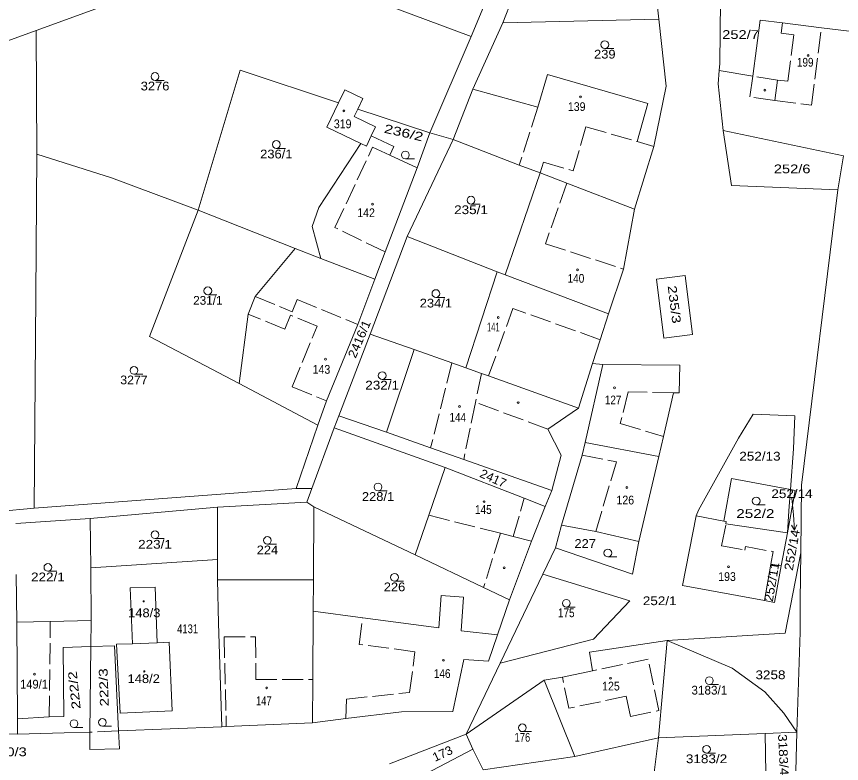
# Model space of a CAD drawing. Extents: x -590528 to -586543, y -1119609 to -1116685.
# Drawn here: x -588764.7 to -588604.8, y -1118121.8 to -1117977 of the extents above; entities that cross this region are included whole.
import ezdxf
from ezdxf.enums import TextEntityAlignment as Align

# ---------------------------------------------------------------- set-up
doc = ezdxf.new("R2010")
doc.units = 0
doc.header["$LTSCALE"] = 0.68
doc.linetypes.add('LONG_DASHED', pattern=[7.5, 6, -1.5])
for name, color, linetype, lineweight in [('1', 7, 'Continuous', 13), ('2', 7, 'LONG_DASHED', 13), ('3', 7, 'Continuous', 13), ('6', 7, 'Continuous', 13)]:
    doc.layers.add(name, color=color, linetype=linetype, lineweight=lineweight)

msp = doc.modelspace()

# ---------------------------------------------------------------- linework, layer by layer
at = {"layer": '1'}
for p, q in [((-588670.43, -1117978.2), (-588661.24, -1117954.68)), ((-588640.24, -1117977.46), (-588641.88, -1117961.86)), ((-588760.88, -1117979.71), (-588719.92, -1117964.64)), ((-588719.92, -1117964.64), (-588676.56, -1117980.86)), ((-588676.56, -1117980.86), (-588669.62, -1117964.03)), ((-588628.23, -1117973.84), (-588628.41, -1117986.05)), ((-588640.24, -1117977.46), (-588638.79, -1117990.47)), ((-588621.96, -1117988.54), (-588620.54, -1117977.65)), ((-588616.22, -1117978.21), (-588620.54, -1117977.65)), ((-588608.69, -1117979.19), (-588616.22, -1117978.21)), ((-588608.69, -1117979.19), (-588600.89, -1117980.09)), ((-588760.74, -1118003.63), (-588760.88, -1117979.71)), ((-588621.96, -1117988.54), (-588628.51, -1117987.46)), ((-588697.59, -1117992.86), (-588701.09, -1117991.21)), ((-588676.24, -1117991.07), (-588680.09, -1118000.83)), ((-588676.24, -1117991.07), (-588663.65, -1117994.53)), ((-588638.79, -1117990.47), (-588641.19, -1118002.14)), ((-588698.58, -1117994.92), (-588684.62, -1117999.55)), ((-588644.44, -1118001.2), (-588642.31, -1117993.82)), ((-588695.1, -1117998.33), (-588699.26, -1117996.34)), ((-588684.62, -1117999.55), (-588680.09, -1118000.83)), ((-588627.73, -1117999.04), (-588626.13, -1118009.73)), ((-588697.94, -1118001.6), (-588706.11, -1118014)), ((-588695.94, -1118000.09), (-588691.55, -1118002.14)), ((-588688.98, -1118019.63), (-588680.09, -1118000.83)), ((-588680.09, -1118000.83), (-588667.27, -1118005.81)), ((-588644.44, -1118001.2), (-588641.19, -1118002.14)), ((-588691.55, -1118002.14), (-588692.35, -1118003.86)), ((-588641.19, -1118002.14), (-588644.92, -1118014.29)), ((-588760.97, -1118031.09), (-588760.74, -1118003.63)), ((-588760.74, -1118003.63), (-588746.32, -1118008.24)), ((-588692.35, -1118003.86), (-588687.06, -1118006.33)), ((-588604.44, -1118003.96), (-588605.52, -1118010.57)), ((-588687.06, -1118006.33), (-588693.23, -1118022.59)), ((-588667.27, -1118005.81), (-588663.2, -1118007.29)), ((-588663.2, -1118007.29), (-588669.98, -1118027.06)), ((-588663.2, -1118007.29), (-588658.01, -1118009.28)), ((-588746.32, -1118008.24), (-588729.5, -1118014.51)), ((-588658.01, -1118009.28), (-588644.92, -1118014.29)), ((-588729.5, -1118014.51), (-588738.93, -1118039.02)), ((-588688.98, -1118019.63), (-588696.16, -1118038.54)), ((-588671.57, -1118026.44), (-588688.98, -1118019.63)), ((-588710.69, -1118021.92), (-588718.43, -1118031.27)), ((-588705.69, -1118023.89), (-588695.24, -1118027.88)), ((-588671.57, -1118026.44), (-588677.59, -1118045.06)), ((-588669.98, -1118027.06), (-588671.57, -1118026.44)), ((-588669.98, -1118027.06), (-588649.96, -1118034.58)), ((-588640.66, -1118027.86), (-588635.09, -1118027.17)), ((-588633.67, -1118038.63), (-588635.09, -1118027.17)), ((-588639.24, -1118039.32), (-588640.66, -1118027.86)), ((-588761.3, -1118072.29), (-588760.97, -1118031.09)), ((-588719.82, -1118034.66), (-588718.43, -1118031.27)), ((-588721.58, -1118048.14), (-588719.82, -1118034.66)), ((-588651.57, -1118039.62), (-588649.96, -1118034.58)), ((-588698.56, -1118036.65), (-588704.64, -1118051.47)), ((-588639.24, -1118039.32), (-588633.67, -1118038.63)), ((-588687.63, -1118041.53), (-588693.02, -1118057.58)), ((-588677.59, -1118045.06), (-588680.35, -1118044.09)), ((-588651.06, -1118044.41), (-588654.48, -1118059.58)), ((-588651.06, -1118044.41), (-588653.04, -1118044.23)), ((-588651.06, -1118044.41), (-588636.16, -1118044.59)), ((-588674.57, -1118046.15), (-588677.59, -1118045.06)), ((-588702.21, -1118054.36), (-588693.02, -1118057.58)), ((-588661.71, -1118056.94), (-588655.81, -1118052.93)), ((-588621.94, -1118054.04), (-588613.85, -1118054.41)), ((-588613.85, -1118054.41), (-588614.13, -1118060.8)), ((-588706.27, -1118056.2), (-588710.52, -1118068.5)), ((-588681.59, -1118064.37), (-588703.16, -1118056.69)), ((-588693.02, -1118057.58), (-588684.44, -1118060.61)), ((-588639.33, -1118058.38), (-588640.24, -1118062.27)), ((-588684.44, -1118060.61), (-588678.03, -1118062.84)), ((-588655.07, -1118062), (-588654.48, -1118059.58)), ((-588640.24, -1118062.27), (-588654.48, -1118059.58)), ((-588655.07, -1118062), (-588659.07, -1118075.61)), ((-588678.03, -1118062.84), (-588660.92, -1118068.83)), ((-588627.63, -1118074.81), (-588626.1, -1118066.55)), ((-588626.1, -1118066.55), (-588614.71, -1118068.65)), ((-588710.52, -1118068.5), (-588761.3, -1118072.29)), ((-588710.52, -1118068.5), (-588707.44, -1118068.44)), ((-588660.92, -1118068.83), (-588662.26, -1118071.95)), ((-588725.75, -1118072.06), (-588708.42, -1118071.12)), ((-588708.42, -1118071.12), (-588707.05, -1118072.01)), ((-588664.89, -1118078.66), (-588662.26, -1118071.95)), ((-588780.43, -1118074), (-588761.3, -1118072.29)), ((-588687.43, -1118081.35), (-588707.05, -1118072.01)), ((-588615.02, -1118072.8), (-588615.29, -1118077.06)), ((-588635.65, -1118087.26), (-588632.98, -1118073.75)), ((-588627.63, -1118074.81), (-588632.98, -1118073.75)), ((-588627.14, -1118074.9), (-588627.63, -1118074.81)), ((-588627.21, -1118075.35), (-588627.14, -1118074.9)), ((-588659.07, -1118075.61), (-588660.21, -1118079.95)), ((-588652.45, -1118076.78), (-588659.07, -1118075.61)), ((-588627.21, -1118075.35), (-588615.29, -1118077.06)), ((-588652.45, -1118076.78), (-588644.07, -1118078.73)), ((-588669.14, -1118090.06), (-588664.89, -1118078.66)), ((-588612.7, -1118080.93), (-588615.74, -1118096.52)), ((-588750.27, -1118083.86), (-588725.75, -1118082.21)), ((-588725.75, -1118082.21), (-588725.75, -1118086.21)), ((-588618.51, -1118083.12), (-588619.75, -1118090.2)), ((-588616.47, -1118083.48), (-588618.51, -1118083.12)), ((-588750.27, -1118083.86), (-588750.25, -1118094.08)), ((-588764.67, -1118094.4), (-588764.74, -1118085.12)), ((-588725.75, -1118086.21), (-588707.17, -1118086.21)), ((-588725.75, -1118086.21), (-588725.55, -1118094.6)), ((-588662.66, -1118085.06), (-588645.83, -1118090.24)), ((-588742.21, -1118098.56), (-588742.68, -1118087.75)), ((-588682.84, -1118095.48), (-588682.38, -1118089.23)), ((-588682.38, -1118089.23), (-588678.06, -1118089.54)), ((-588678.53, -1118096.05), (-588678.06, -1118089.54)), ((-588612.82, -1118090.2), (-588612.82, -1118096.34)), ((-588707.18, -1118092.28), (-588707.26, -1118105.5)), ((-588764.67, -1118094.4), (-588758.16, -1118094.26)), ((-588758.16, -1118094.26), (-588750.25, -1118094.08)), ((-588750.25, -1118094.08), (-588750.3, -1118099.13)), ((-588764.67, -1118094.4), (-588764.52, -1118113.1)), ((-588724.93, -1118114.67), (-588725.55, -1118094.6)), ((-588671.48, -1118096.87), (-588678.53, -1118096.05)), ((-588638.59, -1118097.95), (-588615.74, -1118096.52)), ((-588750.3, -1118099.13), (-588755.67, -1118099.3)), ((-588745.7, -1118098.99), (-588750.3, -1118099.13)), ((-588745.7, -1118098.99), (-588744.93, -1118115.48)), ((-588745.3, -1118098.66), (-588742.21, -1118098.56)), ((-588737.44, -1118098.37), (-588742.21, -1118098.56)), ((-588737.44, -1118098.37), (-588735.09, -1118098.28)), ((-588638.59, -1118097.95), (-588653.64, -1118100.23)), ((-588640.3, -1118116.83), (-588638.59, -1118097.95)), ((-588638.59, -1118097.95), (-588626, -1118103.3)), ((-588755.67, -1118099.3), (-588755.51, -1118112.7)), ((-588653.64, -1118100.23), (-588653.09, -1118103.83)), ((-588670.95, -1118102.33), (-588677.57, -1118116.13)), ((-588653.09, -1118103.83), (-588658.91, -1118105.04)), ((-588626, -1118103.3), (-588619.66, -1118107.86)), ((-588707.26, -1118105.5), (-588707.31, -1118113.9)), ((-588658.91, -1118105.04), (-588662.42, -1118105.6)), ((-588619.66, -1118107.86), (-588615.96, -1118112.01)), ((-588700.86, -1118113.09), (-588690.07, -1118111.74)), ((-588690.07, -1118111.74), (-588680.16, -1118111.68)), ((-588758.35, -1118112.74), (-588755.51, -1118112.7)), ((-588707.31, -1118113.9), (-588700.86, -1118113.09)), ((-588615.96, -1118112.01), (-588613.44, -1118115.68)), ((-588724.93, -1118114.67), (-588744.93, -1118115.48)), ((-588777.31, -1118115.95), (-588764.5, -1118116.07)), ((-588764.5, -1118116.07), (-588755.47, -1118115.84)), ((-588755.47, -1118115.84), (-588750.47, -1118115.71)), ((-588744.93, -1118115.48), (-588744.77, -1118118.94)), ((-588677.57, -1118116.13), (-588692.41, -1118121.83)), ((-588619.63, -1118115.95), (-588619.5, -1118123.67)), ((-588656.48, -1118120.41), (-588640.3, -1118116.83)), ((-588641.32, -1118125.05), (-588640.3, -1118116.83))]:
    msp.add_line(p, q, dxfattribs=at)
for points in [[(-588640.24, -1117977.46), (-588670.43, -1117978.2), (-588676.24, -1117991.07)], [(-588760.88, -1117979.71), (-588779.21, -1117986.35), (-588780.43, -1118074)], [(-588687.06, -1118006.33), (-588684.62, -1117999.55), (-588676.56, -1117980.86)], [(-588628.41, -1117986.05), (-588628.51, -1117987.46), (-588628.69, -1117990.01)], [(-588729.5, -1118014.51), (-588721.38, -1117987.35), (-588702.27, -1117993.69)], [(-588642.31, -1117993.82), (-588661.81, -1117988.18), (-588663.65, -1117994.53)], [(-588604.44, -1118003.96), (-588627.73, -1117999.04), (-588628.69, -1117990.01)], [(-588701.09, -1117991.21), (-588702.27, -1117993.69), (-588704.54, -1117998.45)], [(-588699.26, -1117996.34), (-588698.58, -1117994.92), (-588697.59, -1117992.86)], [(-588696.9, -1118002.09), (-588695.94, -1118000.09), (-588695.1, -1117998.33)], [(-588704.54, -1117998.45), (-588697.94, -1118001.6), (-588696.9, -1118002.09)], [(-588626.13, -1118009.73), (-588605.52, -1118010.57), (-588612.54, -1118067.84)], [(-588706.11, -1118014), (-588707.42, -1118017.69), (-588705.69, -1118023.89)], [(-588644.92, -1118014.29), (-588647.05, -1118025.94), (-588649.96, -1118034.58)], [(-588729.5, -1118014.51), (-588710.69, -1118021.92), (-588705.69, -1118023.89)], [(-588693.23, -1118022.59), (-588695.24, -1118027.88), (-588698.56, -1118036.65)], [(-588704.64, -1118051.47), (-588706.27, -1118056.2), (-588721.58, -1118048.14), (-588738.93, -1118039.02)], [(-588696.16, -1118038.54), (-588702.21, -1118054.36), (-588703.16, -1118056.69)], [(-588680.35, -1118044.09), (-588687.63, -1118041.53), (-588696.16, -1118038.54)], [(-588655.81, -1118052.93), (-588653.04, -1118044.23), (-588651.57, -1118039.62)], [(-588636.16, -1118044.59), (-588636.27, -1118049.93), (-588637.36, -1118049.91), (-588639.33, -1118058.38)], [(-588655.81, -1118052.93), (-588673.2, -1118046.65), (-588674.57, -1118046.15)], [(-588632.98, -1118073.75), (-588632.49, -1118072.69), (-588624.79, -1118058.73), (-588621.94, -1118054.04)], [(-588703.16, -1118056.69), (-588707.44, -1118068.44), (-588708.42, -1118071.12)], [(-588660.92, -1118068.83), (-588659.11, -1118061.98), (-588661.71, -1118056.94)], [(-588640.24, -1118062.27), (-588644.07, -1118078.73), (-588645.31, -1118085.11), (-588660.21, -1118079.95)], [(-588614.13, -1118060.8), (-588614.71, -1118068.65), (-588615.02, -1118072.8)], [(-588687.43, -1118081.35), (-588684.79, -1118073.66), (-588681.59, -1118064.37)], [(-588662.26, -1118071.95), (-588666.29, -1118070.37), (-588681.59, -1118064.37)], [(-588614.71, -1118068.65), (-588613.76, -1118068.83), (-588615.29, -1118077.06)], [(-588612.54, -1118067.84), (-588612.7, -1118080.93), (-588612.82, -1118090.2)], [(-588750.41, -1118074.32), (-588725.75, -1118072.06), (-588725.75, -1118082.21)], [(-588707.05, -1118072.01), (-588707.17, -1118086.21), (-588707.18, -1118092.28)], [(-588750.27, -1118083.86), (-588750.41, -1118074.32), (-588764.82, -1118075.28)], [(-588635.65, -1118087.26), (-588619.75, -1118090.2), (-588617.78, -1118090.56), (-588616.47, -1118083.48), (-588615.29, -1118077.06)], [(-588660.21, -1118079.95), (-588662.66, -1118085.06), (-588670.95, -1118102.33)], [(-588669.14, -1118090.06), (-588674.18, -1118087.66), (-588687.43, -1118081.35)], [(-588742.68, -1118087.75), (-588737.84, -1118087.63), (-588737.44, -1118098.37)], [(-588669.14, -1118090.06), (-588671.48, -1118096.87), (-588673.21, -1118101.92)], [(-588645.83, -1118090.24), (-588652.9, -1118097.65), (-588670.95, -1118102.33)], [(-588682.84, -1118095.48), (-588697.6, -1118093.54), (-588707.18, -1118092.28)], [(-588613.68, -1118123.3), (-588613.44, -1118115.68), (-588612.82, -1118096.34)], [(-588750.3, -1118099.13), (-588750.47, -1118115.71), (-588750.5, -1118119.09), (-588744.77, -1118118.94)], [(-588735.09, -1118098.28), (-588734.56, -1118111.6), (-588744.62, -1118112), (-588745.3, -1118098.66)], [(-588680.16, -1118111.68), (-588677.99, -1118101.61), (-588673.21, -1118101.92)], [(-588656.48, -1118120.41), (-588662.42, -1118105.6), (-588677.57, -1118116.13)], [(-588764.5, -1118116.07), (-588764.52, -1118113.1), (-588758.35, -1118112.74)], [(-588724.93, -1118114.67), (-588724.04, -1118114.63), (-588707.31, -1118113.9)], [(-588677.57, -1118116.13), (-588676.29, -1118118.98), (-588691.92, -1118127.24)], [(-588640.3, -1118116.83), (-588619.63, -1118115.95), (-588613.44, -1118115.68)], [(-588676.29, -1118118.98), (-588674.26, -1118123.02), (-588656.48, -1118120.41)]]:
    msp.add_lwpolyline(points, dxfattribs=at)
at = {"layer": '2'}
for p, q in [((-588610.64, -1117994.16), (-588608.69, -1117979.19)), ((-588614.06, -1117980.51), (-588615.23, -1117989.53)), ((-588617.21, -1117989.28), (-588621.96, -1117988.54)), ((-588617.21, -1117989.28), (-588617.73, -1117993.24)), ((-588615.23, -1117989.53), (-588617.21, -1117989.28)), ((-588617.73, -1117993.24), (-588610.64, -1117994.16)), ((-588663.65, -1117994.53), (-588667.27, -1118005.81)), ((-588656.81, -1118006.89), (-588654.34, -1117998.34)), ((-588654.34, -1117998.34), (-588644.44, -1118001.2)), ((-588662.57, -1118005.22), (-588663.2, -1118007.29)), ((-588662.57, -1118005.22), (-588656.81, -1118006.89)), ((-588658.01, -1118009.28), (-588662.2, -1118021.02)), ((-588693.23, -1118022.59), (-588703, -1118017.87)), ((-588662.2, -1118021.02), (-588647.05, -1118025.94)), ((-588710.33, -1118031.82), (-588698.56, -1118036.65)), ((-588673.2, -1118046.65), (-588668.52, -1118033.56)), ((-588651.57, -1118039.62), (-588668.52, -1118033.56)), ((-588712.68, -1118037.58), (-588719.82, -1118034.66)), ((-588712.68, -1118037.58), (-588711.57, -1118034.87)), ((-588706.43, -1118036.97), (-588711.57, -1118034.87)), ((-588711.26, -1118048.75), (-588706.43, -1118036.97)), ((-588680.35, -1118044.09), (-588684.44, -1118060.61)), ((-588674.57, -1118046.15), (-588675.74, -1118051.79)), ((-588711.26, -1118048.75), (-588704.64, -1118051.47)), ((-588646.16, -1118049.75), (-588647.7, -1118055.89)), ((-588637.36, -1118049.91), (-588646.16, -1118049.75)), ((-588675.74, -1118051.79), (-588678.03, -1118062.84)), ((-588661.71, -1118056.94), (-588675.74, -1118051.79)), ((-588647.7, -1118055.89), (-588639.33, -1118058.38)), ((-588655.07, -1118062), (-588648.43, -1118063.31)), ((-588652.45, -1118076.78), (-588648.43, -1118063.31)), ((-588668.43, -1118077.77), (-588666.29, -1118070.37)), ((-588670.91, -1118077.15), (-588684.79, -1118073.66)), ((-588628.07, -1118079.57), (-588627.21, -1118075.35)), ((-588670.91, -1118077.15), (-588674.18, -1118087.66)), ((-588628.07, -1118079.57), (-588623.55, -1118080.41)), ((-588623.55, -1118080.41), (-588623.42, -1118079.72)), ((-588623.42, -1118079.72), (-588618.06, -1118080.71)), ((-588618.06, -1118080.71), (-588618.51, -1118083.12)), ((-588758.35, -1118112.74), (-588758.16, -1118094.26)), ((-588698.27, -1118098.7), (-588697.6, -1118093.54)), ((-588724.47, -1118097.25), (-588718.36, -1118097.23)), ((-588724.47, -1118097.25), (-588724.04, -1118114.63)), ((-588687.47, -1118100.11), (-588698.27, -1118098.7)), ((-588688.51, -1118108), (-588687.47, -1118100.11)), ((-588642.27, -1118101.57), (-588653.09, -1118103.83)), ((-588640.19, -1118111.53), (-588642.27, -1118101.57)), ((-588657.65, -1118111.08), (-588658.91, -1118105.04)), ((-588700.77, -1118109.31), (-588688.51, -1118108)), ((-588700.77, -1118109.31), (-588700.86, -1118113.09)), ((-588646.55, -1118108.76), (-588657.65, -1118111.08)), ((-588646.55, -1118108.76), (-588645.73, -1118112.69)), ((-588645.73, -1118112.69), (-588640.19, -1118111.53)), ((-588744.93, -1118115.48), (-588750.47, -1118115.71))]:
    msp.add_line(p, q, dxfattribs=at)
for points in [[(-588614.06, -1117980.51), (-588616.47, -1117980.19), (-588616.22, -1117978.21)], [(-588617.73, -1117993.24), (-588622.57, -1117992.53), (-588621.96, -1117988.54)], [(-588703, -1118017.87), (-588695.68, -1118002.31), (-588692.35, -1118003.86)], [(-588718.43, -1118031.27), (-588711.3, -1118034.2), (-588710.33, -1118031.82)], [(-588664.89, -1118078.66), (-588668.43, -1118077.77), (-588670.91, -1118077.15)], [(-588718.36, -1118097.23), (-588718.33, -1118105.53), (-588707.26, -1118105.5)]]:
    msp.add_lwpolyline(points, dxfattribs=at)
at = {"layer": '3'}
for p in [(-588614.4, -1118070.33), (-588613.899, -1118076.54)]:
    msp.add_line(p, (-588614.14, -1118073.55), dxfattribs=at)
msp.add_lwpolyline([(-588613.482, -1118075.504), (-588613.899, -1118076.54), (-588614.479, -1118075.583)], dxfattribs=at)
at = {"layer": '6'}
for p, q in [((-588650.68, -1117983.17), (-588648.93, -1117983.17)), ((-588737.85, -1117989.35), (-588736.1, -1117989.35)), ((-588714.35, -1118002.53), (-588712.6, -1118002.53)), ((-588689.34, -1118004.56), (-588687.59, -1118004.56)), ((-588676.61, -1118013.33), (-588674.86, -1118013.33)), ((-588727.62, -1118030.9), (-588725.87, -1118030.9)), ((-588683.42, -1118031.43), (-588681.67, -1118031.43)), ((-588741.94, -1118046.33), (-588740.19, -1118046.33)), ((-588693.83, -1118047.33), (-588692.08, -1118047.33)), ((-588694.63, -1118068.93), (-588692.88, -1118068.93)), ((-588621.34, -1118071.64), (-588619.59, -1118071.64)), ((-588737.86, -1118078.19), (-588736.11, -1118078.19)), ((-588716.07, -1118079.29), (-588714.32, -1118079.29)), ((-588650.09, -1118081.74), (-588648.34, -1118081.74)), ((-588758.62, -1118084.52), (-588756.87, -1118084.52)), ((-588691.44, -1118086.45), (-588689.69, -1118086.45)), ((-588658.15, -1118091.47), (-588656.4, -1118091.47)), ((-588630.42, -1118106.47), (-588628.67, -1118106.47)), ((-588753.57, -1118114.81), (-588751.82, -1118114.81)), ((-588748.05, -1118114.57), (-588746.3, -1118114.57)), ((-588666.65, -1118115.61), (-588664.9, -1118115.61)), ((-588630.96, -1118119.77), (-588629.21, -1118119.77))]:
    msp.add_line(p, q, dxfattribs=at)
for centre, radius in [((-588650.68, -1117982.42), 0.75), ((-588611.2802, -1117984.5004), 0.175), ((-588737.85, -1117988.6), 0.75), ((-588619.6502, -1117991.2404), 0.175), ((-588655.4002, -1117992.5604), 0.175), ((-588701.2402, -1117995.2704), 0.175), ((-588714.35, -1118001.78), 0.75), ((-588689.34, -1118003.81), 0.75), ((-588676.61, -1118012.58), 0.75), ((-588695.6902, -1118013.3404), 0.175), ((-588655.9502, -1118026.0904), 0.175), ((-588727.62, -1118030.15), 0.75), ((-588683.42, -1118030.68), 0.75), ((-588671.3302, -1118035.3104), 0.175), ((-588704.8102, -1118043.4004), 0.175), ((-588741.94, -1118045.58), 0.75), ((-588693.83, -1118046.58), 0.75), ((-588648.7902, -1118048.9504), 0.175), ((-588678.8502, -1118052.5604), 0.175), ((-588667.4802, -1118051.8304), 0.175), ((-588694.63, -1118068.18), 0.75), ((-588646.3902, -1118068.2704), 0.175), ((-588621.34, -1118070.89), 0.75), ((-588674.0802, -1118071.0204), 0.175), ((-588737.86, -1118077.44), 0.75), ((-588716.07, -1118078.54), 0.75), ((-588650.09, -1118080.99), 0.75), ((-588758.62, -1118083.77), 0.75), ((-588670.1802, -1118083.8304), 0.175), ((-588626.7002, -1118083.6404), 0.175), ((-588691.44, -1118085.7), 0.75), ((-588740.0501, -1118090.3502), 0.1172), ((-588658.15, -1118090.72), 0.75), ((-588681.9602, -1118101.7804), 0.175), ((-588739.9401, -1118103.9302), 0.1172), ((-588761.2302, -1118104.4804), 0.175), ((-588649.5702, -1118105.2704), 0.175), ((-588630.42, -1118105.72), 0.75), ((-588716.2202, -1118107.1404), 0.175), ((-588753.57, -1118114.06), 0.75), ((-588748.05, -1118113.82), 0.75), ((-588666.65, -1118114.86), 0.75), ((-588630.96, -1118119.02), 0.75)]:
    msp.add_circle(centre, radius, dxfattribs=at)

# ---------------------------------------------------------------- texts
at = {"layer": '3'}
for s, width, p in [('252/7', 1.25, (-588624.37, -1117981.32)), ('239', 1.1, (-588650.6805, -1117985.12)), ('199', 0.85, (-588611.84, -1117986.69)), ('3276', 1.1, (-588737.8505, -1117991.3)), ('139', 0.9, (-588656.13, -1117995.29)), ('319', 0.9, (-588701.49, -1117998.62)), ('236/1', 1.1, (-588714.3505, -1118004.48)), ('252/6', 1.25, (-588614.37, -1118007.36)), ('142', 0.9, (-588696.9505, -1118015.86)), ('235/1', 1.15, (-588676.6105, -1118015.28)), ('140', 0.85, (-588656.2705, -1118028.58)), ('234/1', 1.1, (-588683.4205, -1118033.38)), ('141', 0.65, (-588672.29, -1118038.03)), ('143', 0.9, (-588705.6, -1118046.23)), ('3277', 1.05, (-588741.9405, -1118048.28)), ('232/1', 1.15, (-588693.83, -1118049.28)), ('127', 0.85, (-588649.0705, -1118052.16)), ('144', 0.85, (-588679.18, -1118055.53)), ('252/13', 1.15, (-588620.6105, -1118063.06)), ('252/14', 1.15, (-588614.3995, -1118070.33)), ('228/1', 1.1, (-588694.63, -1118070.88)), ('126', 0.9, (-588646.7105, -1118071.56)), ('145', 0.85, (-588674.2205, -1118073.4)), ('252/2', 1.3, (-588621.5005, -1118074.18)), ('223/1', 1.15, (-588737.86, -1118080.14)), ('227', 1.1, (-588654.48, -1118079.99)), ('224', 1.1, (-588716.07, -1118081.24)), ('222/1', 1.15, (-588758.62, -1118086.47)), ('193', 0.9, (-588626.99, -1118086.4)), ('226', 1.1, (-588691.44, -1118088.4)), ('252/1', 1.15, (-588640.04, -1118091.09)), ('148/3', 1.1, (-588739.9395, -1118093.43)), ('175', 0.85, (-588658.1505, -1118093.42)), ('4131', 0.8, (-588731.54, -1118096.52)), ('146', 0.85, (-588682.2, -1118105.2)), ('3258', 1.15, (-588618.57, -1118105.44)), ('149/1', 0.95, (-588761.31, -1118107.26)), ('148/2', 1.1, (-588740.05, -1118106.19)), ('125', 0.9, (-588649.4905, -1118107.63)), ('147', 0.8, (-588716.7705, -1118110.48)), ('176', 0.8, (-588666.6505, -1118117.56)), ('2360/3', 1.25, (-588767.0605, -1118120.37)), ('3183/2', 1.15, (-588630.9605, -1118121.72))]:
    msp.add_text(s, height=1.7, dxfattribs=dict(at, width=width)).set_placement(p, align=Align.CENTER)
for s, rotation, width, p in [('236/2', 346.983, 1.35, (-588689.839, -1118000.3242)), ('235/3', 277.14, 1.3, (-588638.0365, -1118032.8949)), ('2416/1', 66.864, 1.1, (-588697.4773, -1118039.827)), ('2417', 335.581, 1.05, (-588672.6594, -1118067.2691)), ('252/14', 80.042, 1.15, (-588613.5639, -1118080.544)), ('252/11', 80.329, 1.1, (-588617.4855, -1118086.7163)), ('222/3', 92.017, 1.3, (-588746.9407, -1118107.0004)), ('222/2', 96.085, 1.3, (-588752.6598, -1118107.4801)), ('3183/4', 272.671, 1.15, (-588616.9179, -1118120.1294)), ('173', 24.866, 1.05, (-588681.7829, -1118120.6343))]:
    msp.add_text(s, height=1.7, rotation=rotation, dxfattribs=dict(at, width=width)).set_placement(p, align=Align.CENTER)
for s, p in [('231/1', (-588727.6205, -1118032.85)), ('3183/1', (-588630.42, -1118108.42))]:
    msp.add_text(s, height=1.7, dxfattribs=at).set_placement(p, align=Align.CENTER)

doc.saveas('drawing.dxf')
